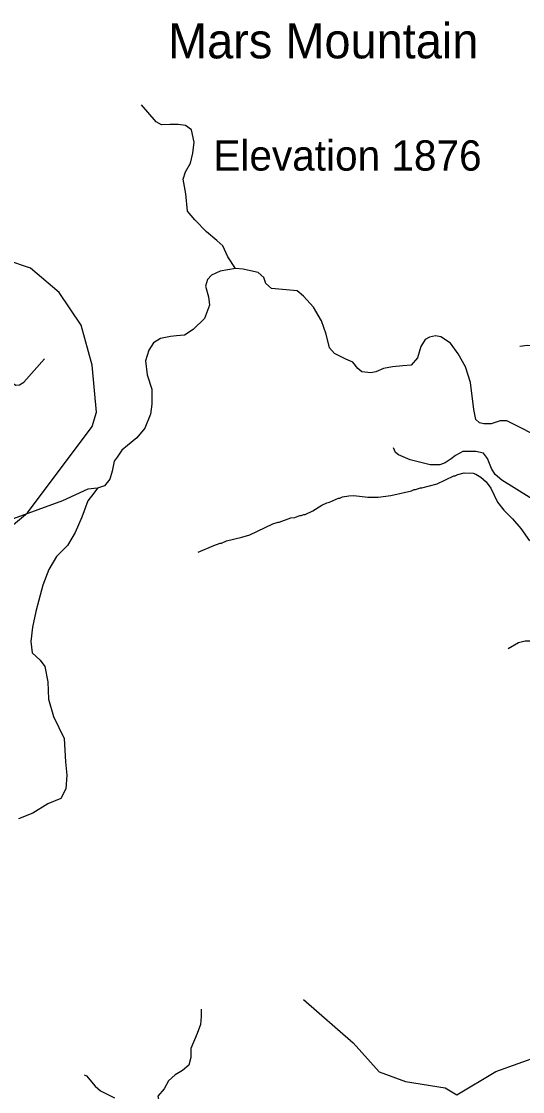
# Model space of a CAD drawing. Extents: x 1248224 to 1454986, y 825081 to 985870.
# Drawn here: x 1318874 to 1322016, y 851342 to 858051 of the extents above; entities that cross this region are included whole.
import ezdxf

# ---------------------------------------------------------------- set-up
doc = ezdxf.new("R2010")
doc.units = 0
for name, color, linetype in [('Exist Geographical Mountain Summit Elevation Number Label', 7, 'Continuous'), ('Exist Geographical Mountain Summit Label', 7, 'Continuous'), ('Exist Hydrographic Misc Water Feature', 7, 'Continuous'), ('Exist Road Non-System Type 51', 7, 'Continuous')]:
    doc.layers.add(name, color=color, linetype=linetype)

msp = doc.modelspace()

# ---------------------------------------------------------------- linework, layer by layer
at = {"layer": 'Exist Hydrographic Misc Water Feature'}
for points in [[(1318656.8, 854759.6), (1318911.8, 854971.1), (1319316.8, 855511.2), (1319343.8, 855602.6), (1319316.8, 855895.3), (1319247.8, 856146.2), (1319110.8, 856352.5), (1318930.8, 856503.8), (1318632.7, 856605)], [(1319982.4, 854724.1), (1320079.3, 854765.8), (1320119.7, 854780.9), (1320127.7, 854780.7), (1320160, 854795.9), (1320256.6, 854817.6), (1320304.9, 854832.5), (1320450.5, 854901.1), (1320482.8, 854912.3), (1320490.8, 854912.2), (1320563.4, 854938.5), (1320587.4, 854941.9), (1320619.6, 854953.1), (1320627.6, 854952.9), (1320643.8, 854960.6), (1320651.8, 854960.4), (1320700.3, 854983.2), (1320757.1, 855017.9), (1320789.5, 855033.1), (1320805.6, 855036.7), (1320862.2, 855063.4), (1320870.2, 855063.2), (1320886.3, 855070.8), (1320926.5, 855077.9), (1320958.6, 855079.1), (1321046.4, 855069.1), (1321110.3, 855069.6), (1321190.6, 855079.7), (1321319.3, 855108.7), (1321335.4, 855116.3), (1321343.4, 855116.1), (1321375.7, 855127.4), (1321383.7, 855127.2), (1321480.2, 855152.9), (1321585.4, 855202.4), (1321593.4, 855202.3), (1321609.5, 855209.9), (1321649.8, 855220.9), (1321705.8, 855219.6), (1321721.7, 855213.2), (1321753.3, 855194.5), (1321786.6, 855165.7), (1321815.7, 855125.1), (1321857.7, 855038.1), (1321898.5, 854987.1), (1321953.3, 854931.9), (1322003.9, 854872.7), (1322058.2, 854795.4)], [(1320641.9, 851919.5), (1320952.9, 851647.4), (1321115.9, 851466.8), (1321280.9, 851404.4), (1321529.9, 851366.6), (1321603.9, 851322.4), (1321848.9, 851468.5), (1322126.9, 851568), (1322268.9, 851565.1), (1322441.9, 851512.4), (1322779.9, 851328.3), (1322999.9, 851090.9), (1323143, 851147.1), (1323600.9, 851502.3), (1324569.9, 851555), (1325536, 851880.3), (1325924, 852039.9), (1326272, 851973.9)], [(1319268.2, 851447.4), (1319282.1, 851441), (1319336.6, 851375.8), (1319369.9, 851347), (1319457, 851303)]]:
    msp.add_lwpolyline(points, dxfattribs=at)
at = {"layer": 'Exist Road Non-System Type 51'}
for points in [[(1320215.8, 856501.4), (1320167.2, 856574.7), (1320137.4, 856645.1), (1320099.5, 856677.6), (1320034.6, 856731.8), (1319961.5, 856807.6), (1319915.5, 856861.8), (1319904.7, 856970.1), (1319888.5, 857062.2), (1319902, 857108.2), (1319934.5, 857162.4), (1319948, 857224.7), (1319956.1, 857295.1), (1319939.9, 857370.9), (1319902, 857398), (1319856, 857406.1), (1319804.6, 857406.1), (1319753.1, 857403.4), (1319718, 857422.4), (1319625.9, 857528)], [(1320215.8, 856501.4), (1320119.2, 856485.3), (1320065.5, 856461.1), (1320041.3, 856434.2), (1320027.9, 856391.3), (1320046.7, 856324.1), (1320052.1, 856273.1), (1320022.5, 856189.8), (1319950.1, 856120), (1319896.4, 856085.1), (1319845.4, 856079.7), (1319807.8, 856077), (1319746.1, 856063.6), (1319703.1, 856036.7), (1319673.6, 855991), (1319652.1, 855923.9), (1319662.9, 855835.2), (1319692.4, 855746.6), (1319692.4, 855652.6), (1319684.3, 855588.1), (1319646.8, 855502.2), (1319598.5, 855440.4), (1319539.4, 855392), (1319504.5, 855362.5), (1319475, 855319.5), (1319456.2, 855295.4), (1319442.8, 855230.9), (1319429.4, 855182.5), (1319394.5, 855139.6), (1319351.5, 855126.1)], [(1320983.4, 855875.5), (1320951.2, 855915.8), (1320908.3, 855934.6), (1320835.8, 855969.6), (1320806.3, 856004.5), (1320784.8, 856090.4), (1320755.3, 856173.7), (1320704.3, 856259.6), (1320642.6, 856329.5), (1320602.3, 856361.7), (1320511, 856369.8), (1320441.3, 856377.8), (1320406.4, 856407.4), (1320392.9, 856445), (1320358, 856477.2), (1320309.7, 856488), (1320264.1, 856498.7), (1320215.8, 856501.4)], [(1322161.7, 855424.3), (1321917.5, 855547.8), (1321874.6, 855547.8), (1321818.2, 855529), (1321772.6, 855529), (1321745.7, 855534.4), (1321721.6, 855555.9), (1321710.8, 855617.7), (1321689.4, 855786.9), (1321657.1, 855886.3), (1321611.5, 855966.9), (1321563.2, 856034), (1321504.1, 856074.3), (1321469.3, 856079.7), (1321431.7, 856071.6), (1321404.8, 856058.2), (1321378, 856012.5), (1321356.5, 855942.7), (1321316.3, 855897), (1321265.3, 855891.7), (1321200.8, 855886.3), (1321144.5, 855875.5), (1321096.2, 855854.1), (1321064, 855848.7), (1321007.6, 855854.1), (1320983.4, 855875.5)], [(1323173.3, 855180.7), (1323003.9, 855306.2), (1322851.6, 855437.1), (1322696.7, 855589.5), (1322560.5, 855728.5), (1322400.2, 855872.8), (1322366.5, 855906.3), (1322286.4, 855935.7), (1322160.9, 855994.6), (1322112.8, 856013.3), (1322046, 856018.6), (1321997.9, 856013.3)], [(1318369.2, 855201.3), (1318359.4, 855296.4), (1318356.7, 855320.8), (1318359.4, 855353.3), (1318378.4, 855375), (1318413.5, 855418.3), (1318419, 855458.9), (1318419, 855529.3), (1318394.6, 855640.4), (1318383.8, 855743.3), (1318386.5, 855827.2), (1318413.5, 855851.6), (1318486.6, 855889.5), (1318532.6, 855894.9), (1318570.5, 855900.4), (1318624.6, 855892.2), (1318640.9, 855881.4), (1318703.1, 855859.7), (1318751.8, 855829.9), (1318822.2, 855781.2), (1318838.4, 855770.4), (1318862.8, 855773.1), (1318889.8, 855789.3), (1319019.7, 855935.6)], [(1322353.8, 854461.6), (1322334.6, 854595.3), (1322307.8, 854707.6), (1322278.5, 854793.1), (1322230.4, 854873.3), (1322163.6, 854982.9), (1322118.2, 855036.4), (1322056.8, 855068.4), (1321885.8, 855175.4), (1321843.1, 855210.1), (1321821.7, 855247.5), (1321795, 855311.7), (1321771, 855343.8), (1321722.9, 855354.5), (1321640.1, 855354.5), (1321594.7, 855330.4), (1321568, 855309), (1321530.6, 855285), (1321495.9, 855271.6), (1321437.1, 855271.6), (1321311.6, 855303.7), (1321236.8, 855333.1), (1321218.1, 855349.1), (1321207.4, 855378.5)], [(1319351.5, 855126.1), (1319289.8, 855118.1), (1319131.4, 855045.5), (1318822.8, 854932.7), (1318653.7, 854887.1), (1318573.1, 854876.3), (1318519.5, 854879), (1318495.3, 854895.1), (1318481.9, 854930), (1318492.6, 854983.8), (1318500.7, 855069.7), (1318487.3, 855120.8), (1318441.6, 855161), (1318369.2, 855201.3)], [(1319351.5, 855126.1), (1319327.4, 855093.9), (1319289.8, 855045.6), (1319252.2, 854943.5), (1319212, 854846.8), (1319163.6, 854766.2), (1319093.9, 854696.4), (1319045.5, 854615.8), (1319008, 854516.4), (1318983.8, 854422.4), (1318965, 854352.6), (1318943.5, 854253.2), (1318932.8, 854164.5), (1318940.9, 854092), (1318991.9, 854046.3), (1319021.4, 854006.1), (1319040.2, 853912), (1319042.9, 853801.9), (1319075.1, 853694.5), (1319142.2, 853554.8), (1319150.2, 853409.7), (1319158.3, 853326.5), (1319152.9, 853240.5), (1319120.7, 853178.7), (1319040.2, 853146.5), (1318946.2, 853087.4), (1318855, 853052.5)], [(1322361, 854104.8), (1322315, 854099.7), (1322234.3, 854117), (1322142.1, 854148.7), (1322096, 854160.2), (1322067.1, 854166), (1322032.6, 854166), (1321989.3, 854154.5), (1321925.9, 854117)], [(1320000.4, 851858.2), (1320000.8, 851812.2), (1319995.7, 851763.1), (1319975, 851706.2), (1319936.3, 851613.2), (1319936.3, 851556.3), (1319923.3, 851507.2), (1319884.6, 851473.5), (1319838.1, 851447.7), (1319796.7, 851408.9), (1319768.3, 851359.8), (1319729.6, 851313.2), (1319737.3, 851269.3), (1319783.8, 851202.1), (1319801.9, 851127.1), (1319843.3, 851072.8), (1319905.3, 851026.3), (1319941.4, 850995.2), (1319962.1, 850946.1), (1319962.1, 850847.9)]]:
    msp.add_lwpolyline(points, dxfattribs=at)

# ---------------------------------------------------------------- texts
at = {"layer": 'Exist Geographical Mountain Summit Elevation Number Label'}
msp.add_text('Elevation 1876', height=190, dxfattribs=at).set_placement((1320077.5, 857115.9))
at = {"layer": 'Exist Geographical Mountain Summit Label'}
msp.add_text('Mars Mountain', height=220, dxfattribs=at).set_placement((1319793, 857819.7))

doc.saveas('drawing.dxf')
